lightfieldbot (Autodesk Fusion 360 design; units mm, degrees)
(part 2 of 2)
sketch "Sketch17" plane through (-13.3, 0, 0) normal (1, 0, 0) x axis (0, 1, 0)
  line L1 (-82.1325, 19.3384) -> (-83.6325, 19.3384)
  line L2 (-82.1325, 87.5884) -> (-82.1325, 19.3384)
  line L3 (-88.3325, 87.5884) -> (-82.1325, 87.5884)
  line L4 (-88.3325, 84.0884) -> (-88.3325, 87.5884)
  line L5 (-93.3325, 84.0884) -> (-88.3325, 84.0884)
  line L6 (-93.3325, 87.5884) -> (-93.3325, 84.0884)
  line L7 (-100.6325, 87.5884) -> (-93.3325, 87.5884)
  line L8 (-100.6325, 56.1384) -> (-100.6325, 87.5884)
  line L9 (-97.9325, 56.1384) -> (-100.6325, 56.1384)
  line L10 (-97.9325, 52.7884) -> (-97.9325, 56.1384)
  line L11 (-95.9325, 52.7884) -> (-97.9325, 52.7884)
  line L12 (-95.9325, 51.4993) -> (-95.9325, 52.7884)
  line L13 (-100.6325, 51.4993) -> (-95.9325, 51.4993)
  line L14 (-100.6325, 16.5884) -> (-100.6325, 51.4993)
  line L15 (-90.5823, 16.5884) -> (-100.6325, 16.5884)
  line L16 (-83.6325, 16.5884) -> (-90.5823, 16.5884)
  line L17 (-83.6325, 19.3384) -> (-83.6325, 16.5884)
  line L18 (-100.6325, 50.0972) -> (-82.1325, 50.0972)
  line L19 (-100.6325, 19.3384) -> (-83.6325, 19.3384)
  circle C1 centre (-85.8625, 82.8284) radius 1.47
extrude "Extrude50" cut sketch "Sketch17" profile of L1 L2 L14 L18 L19 against normal blind 2
fillet "Fillet10" radius 1.5
position "Position12" RotateAboutZ -90
extrude "Extrude10" cut of existing geometry blind -2
sketch "Sketch18" plane through (-16.7262, 0, 0) normal (-1, 0, 0) x axis (0, -1, 0)
  line L1 (82.1325, -12.4116) -> (82.1325, 84.5884)
  line L2 (99.6325, -12.4116) -> (82.1325, -12.4116)
  line L3 (99.6325, 84.5884) -> (99.6325, -12.4116)
  line L4 (82.1325, 84.5884) -> (99.6325, 84.5884)
  circle C1 centre (85.8625, 82.8284) radius 1.47
  circle C2 centre (85.8625, 82.8284) radius 2.65
  dimension "d439" diameter C2 = 5.3
position "Position14"
sketch "Sketch19" plane through (0, -82.1325, 0) normal (0, 1, 0) x axis (-1, 0, 0)
  line L1 (15.3, 19.3384) -> (15.3, 48.5972)
  line L2 (15.3002, 19.3384) -> (15.3, 19.3384)
  line L3 (15.3002, -15.6616) -> (15.3002, 19.3384)
  line L4 (-13.3002, -15.6616) -> (15.3002, -15.6616)
  line L5 (-13.3002, 16.5884) -> (-13.3002, -15.6616)
  line L6 (-13.3, 16.5884) -> (-13.3002, 16.5884)
  line L7 (-13.3, 29.3184) -> (-13.3, 16.5884)
  line L8 (-16.7262, -12.4116) -> (-16.7262, 29.3184)
  line L9 (11.7262, -17.4116) -> (-11.7262, -17.4116)
  line L10 (16.7262, 84.5884) -> (16.7262, -12.4116)
  line L11 (-11.7262, 89.5884) -> (11.7262, 89.5884)
  line L12 (-13.3, 87.5884) -> (-13.3, 38.2584)
  line L13 (13.3, 87.5884) -> (-13.3, 87.5884)
  line L14 (13.3, 51.4256) -> (13.3, 87.5884)
  line L15 (15.7262, 87.5884) -> (13.3, 87.5884)
  line L16 (-15.7262, 87.5884) -> (-13.3, 87.5884)
  line L17 (13.3, 78.3411) -> (16.7262, 78.3411)
  line L18 (-16.7262, 78.3411) -> (-13.3, 78.3411)
  line L19 (-16.7262, 29.3184) -> (-13.3, 29.3184)
  line L20 (-16.7262, 38.2584) -> (-16.7262, 84.5884)
  line L21 (-13.3, 38.2584) -> (-16.7262, 38.2584)
  line L22 (16.7262, 26.1122) -> (16.7262, 22.8622)
  line L23 (15.3, 29.1122) -> (16.7262, 29.1122)
  line L24 (16.7262, 19.8622) -> (15.3, 19.8622)
  line L25 (16.7262, 26.1122) -> (16.7262, 22.8622)
  line L26 (-16.7262, 19.8622) -> (-13.3, 19.8622)
  arc A1 centre (14.8, 51.4256) radius 1.5 clockwise from (14.3, 50.0114) to (13.3, 51.4256)
  arc A2 centre (13.8, 48.5972) radius 1.5 clockwise from (14.3, 50.0114) to (15.3, 48.5972)
  arc A3 centre (-11.7262, -12.4116) radius 5 clockwise from (-11.7262, -17.4116) to (-16.7262, -12.4116)
  arc A4 centre (11.7262, -12.4116) radius 5 clockwise from (16.7262, -12.4116) to (11.7262, -17.4116)
  arc A5 centre (11.7262, 84.5884) radius 5 clockwise from (11.7262, 89.5884) to (16.7262, 84.5884)
  arc A6 centre (-11.7262, 84.5884) radius 5 clockwise from (-16.7262, 84.5884) to (-11.7262, 89.5884)
  point P40 (16.7262, 26.1122)
  point P39 (16.7262, 22.8622)
  dimension "d442" distance P40 L23 = 3
  dimension "d443" distance P39 L24 = 3
extrude "Extrude51" add sketch "Sketch19" profile of L1 L7 L8 L10 A5 A6 L12 L14 L15 L16 L17 L18 L19 L20 L22 L23 L24 L25 L26 along normal blind 6
sketch "Sketch20" plane through (-16.7262, 0, 0) normal (-1, 0, 0) x axis (0, -1, 0)
  line L1 (82.1325, 29.1122) -> (82.1325, 78.3411)
  line L2 (76.1325, 29.1122) -> (82.1325, 29.1122)
  line L3 (76.1325, 19.8622) -> (76.1325, 29.1122)
  line L4 (82.1325, 19.8622) -> (76.1325, 19.8622)
  line L5 (82.1325, -12.4116) -> (82.1325, 19.8622)
  line L6 (99.6325, -12.4116) -> (82.1325, -12.4116)
  line L7 (99.6325, 84.5884) -> (99.6325, -12.4116)
  line L8 (76.1325, 84.5884) -> (99.6325, 84.5884)
  line L9 (76.1325, 78.3411) -> (76.1325, 84.5884)
  line L10 (82.1325, 78.3411) -> (76.1325, 78.3411)
  line L11 (82.1325, 51.4256) -> (100.6325, 51.4256)
  line L12 (82.1325, 78.3411) -> (82.1325, 51.4256)
  line L13 (76.1325, 78.3411) -> (82.1325, 78.3411)
  line L14 (76.1325, 87.5884) -> (76.1325, 78.3411)
  line L15 (82.1325, 87.5884) -> (76.1325, 87.5884)
  line L16 (88.3325, 87.5884) -> (82.1325, 87.5884)
  line L17 (88.3325, 84.0884) -> (88.3325, 87.5884)
  line L18 (93.3325, 84.0884) -> (88.3325, 84.0884)
  line L19 (93.3325, 87.5884) -> (93.3325, 84.0884)
  line L20 (100.6325, 87.5884) -> (93.3325, 87.5884)
  line L21 (100.6325, 56.1384) -> (100.6325, 87.5884)
  line L22 (97.9325, 56.1384) -> (100.6325, 56.1384)
  line L23 (97.9325, 52.7884) -> (97.9325, 56.1384)
  line L24 (95.9325, 52.7884) -> (97.9325, 52.7884)
  line L25 (95.9325, 51.4993) -> (95.9325, 52.7884)
  line L26 (100.6325, 51.4993) -> (95.9325, 51.4993)
  line L27 (100.6325, 51.4256) -> (100.6325, 51.4993)
  line L28 (83.6325, 19.3384) -> (83.6325, 20.8384)
  line L29 (82.1325, 19.3384) -> (83.6325, 19.3384)
  line L30 (82.1325, 19.8622) -> (82.1325, 19.3384)
  line L31 (76.1325, 19.8622) -> (82.1325, 19.8622)
  line L32 (76.1325, 29.1122) -> (76.1325, 19.8622)
  line L33 (82.1325, 29.1122) -> (76.1325, 29.1122)
  line L34 (82.1325, 48.5972) -> (82.1325, 29.1122)
  line L35 (100.6325, 48.5972) -> (82.1325, 48.5972)
  line L36 (100.6325, 20.8384) -> (100.6325, 48.5972)
  line L37 (83.6325, 20.8384) -> (100.6325, 20.8384)
  line L38 (76.1325, 38.2584) -> (76.1325, 19.8622)
  line L39 (82.1325, 38.2584) -> (76.1325, 38.2584)
  line L40 (82.1325, 78.3411) -> (82.1325, 38.2584)
  line L41 (76.1325, 78.3411) -> (82.1325, 78.3411)
  line L42 (76.1325, 84.5884) -> (76.1325, 78.3411)
  line L43 (99.6325, 84.5884) -> (76.1325, 84.5884)
  line L44 (99.6325, -12.4116) -> (99.6325, 84.5884)
  line L45 (82.1325, -12.4116) -> (99.6325, -12.4116)
  line L46 (82.1325, 19.8622) -> (82.1325, -12.4116)
  line L47 (76.1325, 19.8622) -> (82.1325, 19.8622)
  circle C1 centre (80.105, 82.8284) radius 1.625
  circle C2 centre (85.8625, 82.8284) radius 1.47
  circle C3 centre (85.8625, 82.8284) radius 1.47
  circle C4 centre (80.105, 82.8284) radius 1.625
  circle C5 centre (79.1625, 33.7884) radius 1.47
  circle C6 centre (85.8625, 82.8284) radius 1.47
  circle C7 centre (80.105, 82.8284) radius 1.625
  circle C8 centre (80.105, 82.8284) radius 1.625
  circle C9 centre (80.105, 82.8284) radius 1.625
  circle C10 centre (80.105, 24.4872) radius 1.625
  circle C11 centre (80.105, 82.8284) radius 1.47
  circle C12 centre (80.105, 24.4872) radius 1.47
  dimension "d444" diameter C11 = 2.94
  dimension "d445" diameter C12 = 2.94
extrude "Extrude52" sketch "Sketch20" profile of C11 C12 no distance stored
fillet "Fillet12" radius 1.5
fillet "Fillet13" radius 3
fillet "Fillet14" radius 3
fillet "Fillet15" radius 3
fillet "Fillet16" radius 3
copy_paste "CopyPaste2"
position "Position13" RotateAboutZ 0
sketch "Sketch1" plane through (0, 16.1, 0) normal (0, 1, 0) x axis (-1, 0, 0)
  line L1 (16.7662, 0) -> (-16.7662, 0)
  line L2 (16.7662, 16.7) -> (16.7662, 0)
  line L3 (-16.7662, 16.7) -> (16.7662, 16.7)
  line L4 (-16.7662, 0) -> (-16.7662, 16.7)
  line L5 (18.4162, 0) -> (16.7662, 0)
  line L6 (18.4162, 34.5) -> (18.4162, 0)
  line L7 (-18.4162, 34.5) -> (18.4162, 34.5)
  line L8 (-18.4162, 0) -> (-18.4162, 34.5)
  line L9 (-16.7662, 0) -> (-18.4162, 0)
  point P6 (16.7662, 0)
  point P7 (18.4162, 0)
  point P10 (-18.4162, 0)
  point P11 (-16.7662, 0)
  dimension "d457" distance P6 P7 = 1.65
  dimension "d458" distance P10 P11 = 1.65
  dimension "d459" distance L1 L7 = 34.5
extrude "Extrude1" new body sketch "Sketch1" against normal blind 77 and along normal blind 10
position "Position15"
sketch "Sketch1"
  line L1 (40.999, 30.6626) -> (22.199, 30.6626)
  line L2 (40.999, -52.3374) -> (40.999, 30.6626)
  line L3 (22.199, -52.3374) -> (40.999, -52.3374)
  line L4 (22.199, 30.6626) -> (22.199, -52.3374)
  line L5 (22.199, 26.1626) -> (40.999, 26.1626)
  line L6 (37.599, 29.1626) -> (25.599, 29.1626)
  line L7 (37.599, 27.6626) -> (37.599, 29.1626)
  line L8 (25.599, 27.6626) -> (37.599, 27.6626)
  line L9 (25.599, 29.1626) -> (25.599, 27.6626)
  line L10 (31.599, 29.1626) -> (31.599, 30.6626)
  line L11 (34.599, 27.6626) -> (34.599, 29.1626)
  line L12 (28.599, 27.6626) -> (28.599, 29.1626)
  line L13 (36, -10.8374) -> (26, -10.8374)
  line L14 (31, -10.8374) -> (31, 26.1626)
  line L15 (31, -47.8374) -> (31, -10.8374)
  line L16 (22.199, -47.8374) -> (40.999, -47.8374)
  line L17 (37.599, -50.8374) -> (25.599, -50.8374)
  line L18 (37.599, -49.3374) -> (37.599, -50.8374)
  line L19 (34.599, -49.3374) -> (34.599, -50.8374)
  line L20 (28.599, -49.3374) -> (28.599, -50.8374)
  line L21 (25.599, -49.3374) -> (37.599, -49.3374)
  line L22 (25.599, -50.8374) -> (25.599, -49.3374)
  point P3 (40.999, 30.6626)
  point P4 (40.999, -52.3374)
  point P2 (22.199, 30.6626)
  point P8 (25.599, 29.1626)
  point P9 (37.599, 29.1626)
  point P10 (37.599, 27.6626)
  dimension "d486" distance P3 P4 = 83
  dimension "d487" distance P2 P3 = 18.8
  dimension "d488" distance L1 L5 = 4.5
  dimension "d489" distance P8 P9 = 12
  dimension "d490" distance L1 L6 = 1.5
  dimension "d491" distance P9 P10 = 1.5
  dimension "d492" distance L10 L12 = 3
  dimension "d493" distance L10 L11 = 3
  dimension "d508" distance L3 L16 = 4.5
extrude "Extrude1" new body sketch "Sketch1" profile of L1 L2 L4 L5 L6 L7 L8 L9 L11 L12 L16 blind 1
extrude "Extrude2" new body sketch "Sketch1" profile of L6 L7 L8 L9 L11 L12 blind 1.5
extrude "Extrude3" add sketch "Sketch1" profile of L1 L2 L4 L5 L6 L7 L8 L9 blind 12.5
position "Position16"
extrude "Extrude4" add of existing geometry blind 0.5
sketch "Sketch3" plane through (22.199, 0, 0) normal (-1, 0, 0) x axis (0, -1, 0)
  line L1 (-26.1626, 0) -> (-31.1626, 0)
  line L2 (-26.1626, 12.5) -> (-26.1626, 0)
  line L3 (-31.1626, 12.5) -> (-26.1626, 12.5)
  line L4 (-31.1626, 0) -> (-31.1626, 12.5)
  line L5 (-26.1626, 4) -> (-28.6626, 4)
  line L6 (-31.1626, 4) -> (-28.6626, 4)
  line L7 (-30.6626, 1) -> (47.8374, 1)
  circle C1 centre (-28.6626, 4) radius 1.47
  dimension "d503" diameter C1 = 2.94
  dimension "d522" distance L6 L7 = 3
work_plane "WorkPlane1" RotateAngle -90
mirror "Mirror1"
sketch "Sketch4" plane through (40.999, 0, 0) normal (1, 0, 0) x axis (0, 1, 0)
  line L1 (31.1626, 0) -> (26.1626, 0)
  line L2 (31.1626, 12.5) -> (31.1626, 0)
  line L3 (26.1626, 12.5) -> (31.1626, 12.5)
  line L4 (26.1626, 0) -> (26.1626, 12.5)
  line L5 (-47.8374, 12.5) -> (-47.8374, 0)
  line L6 (30.6626, 1) -> (-47.8374, 1)
  line L7 (-47.8374, 12.5) -> (26.1626, 12.5)
  line L8 (-53, 12.5) -> (-47.8374, 12.5)
  line L9 (-10.8374, 1) -> (-10.8374, 12.5)
  line L10 (14.1626, 1) -> (14.1626, 12.5)
  line L11 (-35.8374, 1) -> (-35.8374, 12.5)
  line L12 (-35.8374, 3) -> (14.1626, 3)
  line L13 (26.1626, 8.7484) -> (-10.8374, 8.7484)
  line L14 (-47.8374, 8.7484) -> (-10.8374, 8.7484)
  dimension "d512" distance L6 L12 = 2
extrude "Extrude6" add sketch "Sketch4" profile of L1 L2 L3 L4 L5 L6 L7 L10 L11 L12 along normal blind 1.5
fillet "Fillet1" radius 8.5
fillet "Fillet4" radius 5.5
fillet "Fillet6" radius 2
fillet "Fillet4" radius 9
fillet "Fillet5" radius 3
shell "Shell2" innerThickness 1.5
extrude "Extrude6" cut of existing geometry blind -3.5
position "Position17"
sketch "Sketch4" plane through (18.4162, 0, 0) normal (1, 0, 0) x axis (0, 1, 0)
  line L1 (23.1, 25.5) -> (23.1, 0)
  line L2 (-60.9, 25.5) -> (23.1, 25.5)
  line L3 (-60.9, 0) -> (-60.9, 25.5)
  line L4 (23.1, 0) -> (-60.9, 0)
  line L5 (-28.5418, 17.3506) -> (-60.9, 17.3506)
  line L6 (-28.5798, 0) -> (-28.5418, 17.3506)
  circle C1 centre (-13.8494, 5.8006) radius 1.4
  circle C2 centre (-13.8494, 5.8006) radius 1.4
  circle C3 centre (13.1, 5.8006) radius 1.4
  circle C4 centre (13.1, 5.8006) radius 1.4
  circle C5 centre (-13.8494, 5.8006) radius 1.9
  circle C6 centre (13.1, 5.8006) radius 1.9
  dimension "d535" diameter C5 = 3.8
  dimension "d536" diameter C6 = 3.8
extrude "Extrude7" sketch "Sketch4" profile of L3 L4 L5 L6 blind -56
fillet "Fillet6" radius 9.5
fillet "Fillet7" radius 3
fillet "Fillet8" radius 3
extrude "Extrude8" sketch "Sketch4" profile of C1 C2 C3 C4 C5 C6 blind -60
position "Position18"
sketch "Sketch5" plane through (0, 26.1, 0) normal (0, 1, 0) x axis (-1, 0, 0)
  line L1 (-15.4162, 0) -> (-15.4162, 25.5)
  line L2 (15.4162, 0) -> (-15.4162, 0)
  line L3 (15.4162, 25.5) -> (15.4162, 0)
  line L4 (-9.4162, 31.5) -> (9.4162, 31.5)
  line L5 (5.6, 18.75) -> (-5.6, 18.75)
  line L6 (5.6, 12.75) -> (5.6, 18.75)
  line L7 (-5.6, 12.75) -> (5.6, 12.75)
  line L8 (-5.6, 18.75) -> (-5.6, 12.75)
  line L9 (9.8, 16.7) -> (-9.8, 16.7)
  line L10 (-16.7662, 16.7) -> (16.7662, 16.7)
  line L11 (0, 18.75) -> (0, 31.5)
  line L12 (-5.6, 15.75) -> (-7.5, 15.7207)
  line L13 (0, 0) -> (0, 12.75)
  arc A1 centre (9.4162, 25.5) radius 6 clockwise from (9.4162, 31.5) to (15.4162, 25.5)
  arc A2 centre (-9.4162, 25.5) radius 6 clockwise from (-15.4162, 25.5) to (-9.4162, 31.5)
  circle C1 centre (-7.5, 15.7207) radius 1.4
  circle C2 centre (7.5, 15.7207) radius 1.4
  point P10 (-5.6, 18.75)
  point P11 (5.6, 18.75)
  point P12 (5.6, 12.75)
  point P20 (-7.5, 15.7207)
  dimension "d539" distance P10 P11 = 11.2
  dimension "d540" distance P11 P12 = 6
  dimension "d541" diameter C1 = 2.8
  dimension "d542" distance L8 P20 = 1.9
extrude "Extrude9" sketch "Sketch5" profile of L5 L6 L7 L8 L9 L10 C1 C2 blind -4
sketch "Sketch6" plane through (18.4162, 0, 0) normal (1, 0, 0) x axis (0, 1, 0)
  line L1 (-60.9, 0) -> (-60.9, 25.5)
  line L2 (22.6626, 17.3506) -> (-60.3374, 17.3506)
  circle C1 centre (20.6626, 21.3506) radius 1.47
  circle C2 centre (-58.3374, 21.3506) radius 1.47
  circle C3 centre (20.6626, 14.8506) radius 1.47
  point P6 (20.6626, 14.8506)
  dimension "d549" diameter C3 = 2.94
  dimension "d550" distance P6 L2 = 2.5
extrude "Extrude10" sketch "Sketch6" profile of C1 C2 blind -39
extrude "Extrude11" sketch "Sketch6" profile of C3 blind -57
position "Position19"
sketch "Sketch2" plane through (0, -67.8625, 0) normal (0, 1, 0) x axis (-1, 0, 0)
  line L1 (16.7662, 198.31) -> (16.7662, 104.12)
  line L2 (-16.7662, 198.31) -> (16.7662, 198.31)
  line L3 (-16.7662, 104.12) -> (-16.7662, 198.31)
  line L4 (16.7662, 104.12) -> (-16.7662, 104.12)
  line L5 (16.7662, 113.12) -> (-16.6858, 113.12)
  line L6 (16.7662, 35.9503) -> (16.7662, 113.12)
  line L7 (-16.6858, 35.9503) -> (16.7662, 35.9503)
  line L8 (-16.6858, 113.12) -> (-16.6858, 35.9503)
  line L9 (16.7662, 142.66) -> (16.7662, 19.7)
  line L10 (-21.5287, 98.615) -> (-21.5287, 101.865)
  line L11 (-21.5287, 110.62) -> (-21.5287, 100.24)
  line L12 (-3.4513, 100.24) -> (-21.5287, 100.24)
  line L13 (-8, 111.62) -> (-12.4593, 111.62)
  circle C1 centre (0, 182.21) radius 6.325
  point P15 (-21.5287, 100.24)
  point P16 (-21.5287, 110.62)
  point P7 (-16.6858, 113.12)
  point P8 (16.7662, 113.12)
  dimension "d571" distance P15 P16 = 10.38
  dimension "d573" distance L5 L13 = 1.5
  dimension "d586" distance P7 P8 = 33.452
position "Position20"
sketch "Sketch5" plane through (22.199, 0, 0) normal (-1, 0, 0) x axis (0, -1, 0)
  line L1 (52.8374, 0) -> (-31.1626, 0)
  line L2 (52.8374, 12.5) -> (52.8374, 0)
  line L3 (47.8374, 12.5) -> (52.8374, 12.5)
  line L4 (47.8374, 1) -> (47.8374, 12.5)
  line L5 (-26.1626, 1) -> (47.8374, 1)
  line L6 (-26.1626, 12.5) -> (-26.1626, 1)
  line L7 (-31.1626, 12.5) -> (-26.1626, 12.5)
  line L8 (-31.1626, 0) -> (-31.1626, 12.5)
  line L9 (-31.1626, 1) -> (-26.1626, 1)
  line L10 (52.8374, 1) -> (47.8374, 1)
extrude "Extrude7" add sketch "Sketch5" profile of L1 L2 L5 L8 L9 L10 along normal blind 3
sketch "Sketch6" plane through (0, 0, 1) normal (0, 0, 1) x axis (-1, 0, 0)
  line L1 (-38.999, -26.1626) -> (-38.999, 47.8374)
  line L2 (-22.199, -26.1626) -> (-38.999, -26.1626)
  line L3 (-22.199, -31.1626) -> (-22.199, -26.1626)
  line L4 (-19.199, -31.1626) -> (-22.199, -31.1626)
  line L5 (-19.199, 52.8374) -> (-19.199, -31.1626)
  line L6 (-22.199, 52.8374) -> (-19.199, 52.8374)
  line L7 (-22.199, 47.8374) -> (-22.199, 52.8374)
  line L8 (-38.999, 47.8374) -> (-22.199, 47.8374)
  line L9 (-22.199, 47.8374) -> (-22.199, -26.1626)
extrude "Extrude8" add sketch "Sketch6" profile of L3 L4 L5 L6 L7 L9 along normal blind 10
fillet "Fillet8" radius 3
fillet "Fillet9" radius 1.5
fillet "Fillet10" radius 1.5
fillet "Fillet11" radius 2
sketch "Sketch7" plane through (19.199, 0, 0) normal (-1, 0, 0) x axis (0, -1, 0)
  line L1 (-31.1626, 9.5) -> (52.8374, 9.5)
  line L2 (-31.1626, 3) -> (-31.1626, 9.5)
  line L3 (49.8374, 0) -> (-28.1626, 0)
  line L4 (52.8374, 9.5) -> (52.8374, 3)
  line L5 (52.9, 8.1494) -> (52.9, 3)
  line L6 (-31.1, 8.1494) -> (52.9, 8.1494)
  line L7 (-31.1, -17.3506) -> (-31.1, 8.1494)
  line L8 (17.5732, -17.3506) -> (-31.1, -17.3506)
  line L9 (20.5627, -9.5208) -> (20.5732, -14.344)
  line L10 (49.9, 0) -> (30.0626, 0)
  line L11 (-26.1626, 3) -> (47.8374, 3)
  line L12 (-26.1626, 11) -> (-26.1626, 3)
  line L13 (47.8374, 11) -> (-26.1626, 11)
  line L14 (47.8374, 3) -> (47.8374, 11)
  arc A1 centre (-28.1626, 3) radius 3 clockwise from (-28.1626, 0) to (-31.1626, 3)
  arc A2 centre (49.8374, 3) radius 3 clockwise from (52.8374, 3) to (49.8374, 0)
  circle C1 centre (50.3374, 4) radius 1.47
  circle C2 centre (-28.6626, 4) radius 1.47
  circle C3 centre (-28.6626, -2.5) radius 1.47
  circle C4 centre (50.3374, 4) radius 1.47
  circle C5 centre (-28.6626, 4) radius 1.47
  circle C6 centre (5.8494, -11.55) radius 1.9
  circle C7 centre (-21.1, -11.55) radius 1.9
  arc A3 centre (49.9, 3) radius 3 clockwise from (52.9, 3) to (49.9, 0)
  arc A4 centre (17.5732, -14.3506) radius 3 clockwise from (20.5732, -14.344) to (17.5732, -17.3506)
  arc A5 centre (30.0626, -9.5) radius 9.5 clockwise from (20.5627, -9.5208) to (30.0626, 0)
extrude "Extrude9" sketch "Sketch7" profile of C1 C2 C4 C5 blind -6.4
fillet "Fillet12" radius 1.5
extrude "Extrude1" new body sketch "Sketch2" profile of L1 L3 L4 L5 L6 L7 L8 L9 along normal blind 11.5
fillet "Fillet1" radius 12.5
fillet "Fillet2" radius 3
fillet "Fillet3" radius 3
shell "Shell1" innerThickness 1.5
sketch "Sketch3" plane through (16.7662, 0, 0) normal (-1, 0, 0) x axis (0, -1, 0)
  line L1 (84.5625, 135.66) -> (84.5625, 3)
  line L2 (70.8625, 145.66) -> (74.5625, 145.66)
  line L3 (67.8625, 19.7) -> (67.8625, 142.66)
  line L4 (46.55, 16.7) -> (64.8625, 16.7)
  line L5 (36.55, 3) -> (36.55, 6.7)
  line L6 (81.5625, 0) -> (39.55, 0)
  line L7 (73.9994, 7.7006) -> (67.9994, 7.7006)
  line L8 (67.9994, 3.9006) -> (73.9994, 3.9006)
  line L9 (47.05, 7.7006) -> (41.05, 7.7006)
  line L10 (41.05, 3.9006) -> (47.05, 3.9006)
  line L11 (74.3625, 104.24) -> (67.8625, 104.24)
  line L12 (74.3625, 96.24) -> (74.3625, 104.24)
  line L13 (67.8625, 96.24) -> (74.3625, 96.24)
  line L14 (67.8625, 104.24) -> (67.8625, 96.24)
  line L15 (74.3625, 45.8988) -> (67.8625, 45.8988)
  line L16 (74.3625, 37.8988) -> (74.3625, 45.8988)
  line L17 (67.8625, 37.8988) -> (74.3625, 37.8988)
  line L18 (67.8625, 45.8988) -> (67.8625, 37.8988)
  arc A1 centre (81.5625, 3) radius 3 clockwise from (84.5625, 3) to (81.5625, 0)
  arc A2 centre (74.5625, 135.66) radius 10 clockwise from (74.5625, 145.66) to (84.5625, 135.66)
  arc A3 centre (70.8625, 142.66) radius 3 clockwise from (67.8625, 142.66) to (70.8625, 145.66)
  arc A4 centre (64.8625, 19.7) radius 3 clockwise from (67.8625, 19.7) to (64.8625, 16.7)
  arc A5 centre (46.55, 6.7) radius 10 clockwise from (36.55, 6.7) to (46.55, 16.7)
  arc A6 centre (39.55, 3) radius 3 clockwise from (39.55, 0) to (36.55, 3)
  arc A7 centre (67.9994, 5.8006) radius 1.9 clockwise from (67.9994, 3.9006) to (67.9994, 7.7006)
  arc A8 centre (73.9994, 5.8006) radius 1.9 clockwise from (73.9994, 7.7006) to (73.9994, 3.9006)
  arc A9 centre (41.05, 5.8006) radius 1.9 clockwise from (41.05, 3.9006) to (41.05, 7.7006)
  arc A10 centre (47.05, 5.8006) radius 1.9 clockwise from (47.05, 7.7006) to (47.05, 3.9006)
  circle C1 centre (70.8625, 100.24) radius 1.625
  circle C2 centre (70.8625, 41.8988) radius 1.625
  circle C3 centre (81.5625, 41.8988) radius 1.625
  circle C4 centre (73.6631, 111.2106) radius 1.9
  circle C5 centre (73.6631, 138.16) radius 1.9
  circle C6 centre (81.5625, 100.24) radius 1.625
  circle C7 centre (70.8625, 100.24) radius 1.47
  circle C8 centre (70.8625, 41.8988) radius 1.47
  point P32 (70.8625, 100.24)
  point P33 (70.8625, 41.8988)
  dimension "d574" distance P32 L11 = 4
  dimension "d575" distance P32 L13 = 4
  dimension "d576" distance P32 L12 = 3.5
  dimension "d577" distance P33 L15 = 4
  dimension "d578" distance P33 L16 = 3.5
  dimension "d579" distance P33 L17 = 4
  dimension "d583" diameter C7 = 2.94
  dimension "d584" diameter C8 = 2.94
extrude "Extrude2" sketch "Sketch3" profile of L3 C1 C2 L11 L12 L13 L14 L15 L16 L17 L18 C7 C8 blind 1.5
work_plane "WorkPlane1"
mirror "Mirror1"
combine "Combine1"
fillet "Fillet4" radius 2
sketch "Sketch1" plane through (0, -103.59, 0) normal (0, -1, 0) x axis (1, 0, 0)
  line L1 (-6.29, 83.85) -> (6.21, 83.85)
  line L2 (-8.29, 95.35) -> (-8.29, 85.85)
  line L3 (6.21, 97.35) -> (-6.29, 97.35)
  line L4 (8.21, 85.85) -> (8.21, 95.35)
  line L5 (6.46, 28.1) -> (-6.54, 28.1)
  line L6 (9.46, 12.1) -> (9.46, 25.1)
  line L7 (-6.54, 9.1) -> (6.46, 9.1)
  line L8 (-9.54, 25.1) -> (-9.54, 12.1)
  line L9 (-14.2662, 5) -> (-14.2662, 102)
  line L10 (11.6862, 2.5) -> (-11.7662, 2.5)
  line L11 (14.1862, 102) -> (14.1862, 5)
  line L12 (-11.7662, 104.5) -> (11.6862, 104.5)
  line L13 (6.46, 28.1) -> (-6.54, 28.1)
  line L14 (9.46, 12.1) -> (9.46, 25.1)
  line L15 (-6.54, 9.1) -> (6.46, 9.1)
  line L16 (-9.54, 25.1) -> (-9.54, 12.1)
  line L17 (5.06, 9.1) -> (5.06, 28.1)
  line L18 (9.46, 22.1) -> (5.06, 22.1)
  line L19 (9.46, 15.1) -> (5.06, 15.1)
  line L20 (0.11, 28.1) -> (5.06, 28.1)
  line L21 (13.2602, 27.9) -> (13.2602, 34)
  line L22 (13.46, 32.1) -> (0.11, 32.1)
  line L23 (13.2602, 7.9) -> (13.2602, 1.75)
  line L24 (0.11, 5.1) -> (13.46, 5.1)
  line L25 (0.11, 9.1) -> (0.11, 5.1)
  line L26 (0.11, 28.1) -> (0.11, 32.1)
  line L27 (13.46, 5.1) -> (13.46, 32.1)
  line L28 (-0.04, 18.6) -> (9.46, 18.6)
  line L29 (5.06, 28.1) -> (5.06, 22.1)
  line L30 (5.06, 9.1) -> (5.06, 15.1)
  arc A1 centre (-6.29, 85.85) radius 2 clockwise from (-6.29, 83.85) to (-8.29, 85.85)
  arc A2 centre (-6.29, 95.35) radius 2 clockwise from (-8.29, 95.35) to (-6.29, 97.35)
  arc A3 centre (6.21, 95.35) radius 2 clockwise from (6.21, 97.35) to (8.21, 95.35)
  arc A4 centre (6.21, 85.85) radius 2 clockwise from (8.21, 85.85) to (6.21, 83.85)
  circle C1 centre (6.81, 30.1) radius 1.25
  circle C2 centre (11.5262, 11.75) radius 1.25
  circle C3 centre (-11.6062, 26.25) radius 1.25
  circle C4 centre (-6.89, 7.1) radius 1.25
  circle C5 centre (-6.89, 30.1) radius 1.25
  circle C6 centre (11.5262, 26.25) radius 1.25
  circle C7 centre (-11.6062, 11.75) radius 1.25
  circle C8 centre (6.81, 7.1) radius 1.25
  arc A5 centre (6.46, 25.1) radius 3 clockwise from (6.46, 28.1) to (9.46, 25.1)
  arc A6 centre (6.46, 12.1) radius 3 clockwise from (9.46, 12.1) to (6.46, 9.1)
  arc A7 centre (-6.54, 12.1) radius 3 clockwise from (-6.54, 9.1) to (-9.54, 12.1)
  arc A8 centre (-6.54, 25.1) radius 3 clockwise from (-9.54, 25.1) to (-6.54, 28.1)
  arc A9 centre (-11.7662, 5) radius 2.5 clockwise from (-11.7662, 2.5) to (-14.2662, 5)
  arc A10 centre (11.6862, 5) radius 2.5 clockwise from (14.1862, 5) to (11.6862, 2.5)
  arc A11 centre (11.6862, 102) radius 2.5 clockwise from (11.6862, 104.5) to (14.1862, 102)
  arc A12 centre (-11.7662, 102) radius 2.5 clockwise from (-14.2662, 102) to (-11.7662, 104.5)
  circle C9 centre (6.81, 30.1) radius 1.25
  circle C10 centre (11.5262, 11.75) radius 1.25
  circle C11 centre (6.81, 7.1) radius 1.25
  circle C12 centre (11.5262, 26.25) radius 1.25
  arc A13 centre (6.46, 25.1) radius 3 clockwise from (6.46, 28.1) to (9.46, 25.1)
  arc A14 centre (6.46, 12.1) radius 3 clockwise from (9.46, 12.1) to (6.46, 9.1)
  arc A15 centre (-6.54, 12.1) radius 3 clockwise from (-6.54, 9.1) to (-9.54, 12.1)
  arc A16 centre (-6.54, 25.1) radius 3 clockwise from (-9.54, 25.1) to (-6.54, 28.1)
  circle C13 centre (-6.89, 30.1) radius 1.25
  circle C14 centre (-11.6062, 26.25) radius 1.25
  circle C15 centre (-11.6062, 11.75) radius 1.25
  circle C16 centre (-6.89, 7.1) radius 1.25
  circle C17 centre (-0.04, 18.6) radius 4.75
  circle C18 centre (6.81, 30.1) radius 0.9
  circle C19 centre (11.5262, 26.25) radius 0.9
  circle C20 centre (11.5262, 11.75) radius 0.9
  circle C21 centre (6.81, 7.1) radius 0.9
  point P72 (0.11, 28.1)
  point P75 (0.11, 32.1)
  point P80 (0.11, 5.1)
  point P81 (0.11, 9.1)
  point P76 (13.46, 32.1)
  point P79 (13.46, 5.1)
  dimension "d588" distance L6 L17 = 4.4
  dimension "d591" distance L5 L18 = 6
  dimension "d594" distance P72 P75 = 4
  dimension "d595" distance P80 P81 = 4
  dimension "d596" distance L6 L27 = 4
  dimension "d597" distance P75 P76 = 13.35
  dimension "d598" distance P79 P80 = 13.35
  dimension "d603" diameter C17 = 9.5
  dimension "d604" diameter C18 = 1.8
  dimension "d605" diameter C19 = 1.8 (= "d604")
  dimension "d606" diameter C20 = 1.8 (= "d604")
  dimension "d607" diameter C21 = 1.8 (= "d604")
extrude "Extrude1" new body sketch "Sketch1" profile of C1 C2 C6 C8 L5 A5 L6 A6 L7 L13 C9 C10 C11 C12 L14 A13 A14 L15 L17 L18 L19 L20 L22 L24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 along normal blind 1
extrude "Extrude2" add sketch "Sketch1" profile of C18 C19 C20 C21 along normal blind 3.5
fillet "Fillet1" radius 4.5
fillet "Fillet3" radius 3
fillet "Fillet4" radius 3.5
fillet "Fillet5" radius 1.25
chamfer "Chamfer1" distance 1
sketch "Sketch1" plane through (0, 16.1, 0) normal (0, 1, 0) x axis (-1, 0, 0)
  line L1 (16.7662, 0) -> (-16.7662, 0)
  line L2 (16.7662, 16.7) -> (16.7662, 0)
  line L3 (-16.7662, 16.7) -> (16.7662, 16.7)
  line L4 (-16.7662, 0) -> (-16.7662, 16.7)
  line L5 (18.4162, 0) -> (16.7662, 0)
  line L6 (18.4162, 34.5) -> (18.4162, 0)
  line L7 (-18.4162, 34.5) -> (18.4162, 34.5)
  line L8 (-18.4162, 0) -> (-18.4162, 34.5)
  line L9 (-16.7662, 0) -> (-18.4162, 0)
  point P6 (16.7662, 0)
  point P7 (18.4162, 0)
  point P10 (-18.4162, 0)
  point P11 (-16.7662, 0)
  dimension "d457_1" distance P6 P7 = 1.65
  dimension "d458_1" distance P10 P11 = 1.65
  dimension "d459_1" distance L1 L7 = 34.5
extrude "Extrude1" new body sketch "Sketch1" against normal blind 72 named "d460_1" and along normal blind 10 named "d462_1"
chamfer "Chamfer2" distance 20
fillet "Fillet14" radius 3
fillet "Fillet15" radius 39.5
fillet "Fillet16" radius 3
shell "Shell2" innerThickness 1.5 named "d527_1"
extrude "Extrude6" cut of existing geometry blind -3.5 named "d528_1"
sketch "Sketch4" plane through (18.4162, 0, 0) normal (1, 0, 0) x axis (0, 1, 0)
  line L1 (-55.9, 0) -> (-55.9, 31.5)
  line L2 (23.0962, 0) -> (-55.9, 0)
  line L3 (-23.9, 17.3506) -> (-55.9, 17.3506)
  line L4 (-23.9, 0) -> (-23.9, 17.3506)
  line L5 (-55.9, 0) -> (-55.9, 31.5)
  line L6 (-55.9, 31.5) -> (4.8574, 31.5)
  line L7 (4.8574, 31.5) -> (12.4555, 23.9019)
  circle C1 centre (-13.8494, 5.8006) radius 1.4
  circle C2 centre (-13.8494, 5.8006) radius 1.4
  circle C3 centre (13.1, 5.8006) radius 1.4
  circle C4 centre (13.1, 5.8006) radius 1.4
  circle C5 centre (-13.8494, 5.8006) radius 1.9
  circle C6 centre (13.1, 5.8006) radius 1.9
  arc A1 centre (-13.3539, -1.9075) radius 36.5 clockwise from (12.4555, 23.9019) to (23.0962, 0)
  dimension "d535_1" diameter C5 = 3.8
  dimension "d536_1" diameter C6 = 3.8
  dimension "d620" distance L4 L5 = 32
extrude "Extrude7" cut sketch "Sketch4" profile of L1 L2 L3 L4 against normal blind 56 named "d530_1"
fillet "Fillet6" radius 9.5 named "d532_1"
fillet "Fillet7" radius 3 named "d533_1"
fillet "Fillet8" radius 15 named "d534_1"
extrude "Extrude8" cut sketch "Sketch4" profile of C1 C2 C3 C4 C5 C6 against normal blind 60 named "d537_1"
position "Position21"
position "Position22"
mirror_component "MirrorComponent2"
derived_instance "DerivedInstance2"
position "Position23"
mirror_component "MirrorComponent3"
derived_instance "DerivedInstance3"
joint_origin "JointOrigin3" OffsetX 0 named "d125_1" OffsetY 0 named "d126_1" OffsetZ 0 named "d127_1" AngleZ 0 named "d128_1"
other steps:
derived_base_feature "DerivedBaseFeature1"
derived_base_feature "DerivedBaseFeature1"
create_component "CreateComponent1"
create_component "CreateComponent2"
create_component "CreateComponent4"
create_component "CreateComponent5"
create_component "CreateComponent6" sketch "Sketch1"
create_component "CreateComponent7"
joint_origin "JointOrigin5" OffsetX 0 OffsetY 0 OffsetZ 0 AngleZ 0
joint_origin "JointOrigin2" OffsetX 0 OffsetY 0 OffsetZ 0 AngleZ 0
create_component "CreateComponent10"
create_component "CreateComponent11"
create_component "CreateComponent12"
create_component "CreateComponent13"
create_component "CreateComponent14"
create_component "CreateComponent16"
create_component "CreateComponent17"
